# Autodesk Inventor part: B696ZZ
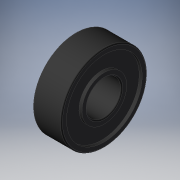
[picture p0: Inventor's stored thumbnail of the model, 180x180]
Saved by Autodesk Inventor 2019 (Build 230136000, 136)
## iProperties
Created: 2022-11
Part Number: B696ZZ
Material: Generic
Catalog Web Link: www.cadenas.de
Description: B6 _ _ ZZ, B6 _ _ AZZ, SB6 _ _ ZZ, SB6 _ _ AZZ, BR _ _ ZZ, SBR _ _ ZZ-Small Ball Bearings - Double Shield Type
Vendor: MISUMI
Document SubType Name: Modeling
Designer: psAdmin
Manufacturer: MISUMI
Mass: 0.647818 g
Surface Area: 6.84496 cm^2
Volume: 0.647818 cm^3
Density: 1 g/cm^3
Appearance: PSOLRGB-175-175-175
Category: PARTsolutions
Company: MISUMI
Title: B696ZZ
Author: Cadenas PARTsolutions
Comments: Small Ball Bearings - Double Shield Type
PSOL_IDENT_0: {$CADENAS_DATA/23d-libs/misumi/metric/12_bearing_holders/sb685zz.prj},219 {VTYP=3D},{NB=B696ZZ},{LIN
PSOL_IDENT_1: A=B696ZZ},{NN=B6 _ _ ZZ, B6 _ _ AZZ, SB6 _ _ ZZ, SB6 _ _ AZZ, BR _ _ ZZ, SBR _ _ ZZ},{DATE=30.06.202
PSOL_IDENT_2: 1 12:59:24},{GEOMDATE=23.07.2013 00:00:00},{VERSION=},{LINEID=120},{WBVAR=MAT},{WBNUMERIC=}  {NB=B69
PSOL_IDENT_3: 6ZZ},{LINA=B696ZZ},{KT=DUMMY},{PN=B696ZZ},{MAT=},{BN=696ZZ},{DD=6.0},{A=3.9530},{BB=0.900},{C=0.900}
PSOL_IDENT_4: ,{D=15},{B=5.0},{RR=0.20},{CR=1350},{COR=530},{CRS=1350},{CRSS=1139},{CORS=530},{CORSS=418},{DS=7.60
PSOL_IDENT_5: },{DDHH=13.40},{R=0.20},{MASS=3.8},{X=0},{BN2=B696ZZ}
NB: B696ZZ
NN: B6 _ _ ZZ, B6 _ _ AZZ, SB6 _ _ ZZ, SB6 _ _ AZZ, BR _ _ ZZ, SBR _ _ ZZ
NT: Small Ball Bearings - Double Shield Type
NBSYN: $PN.
LINA: B696ZZ
CATALOG: Misumi
PN: B696ZZ
MAT: 52100 Bearing Steel
BN: 696ZZ
DD: 6
D: 15
B: 5
RR: 0.2
CR: 1350
COR: 530
DS: 7.6
DDHH: 13.4
R: 0.2
MASS: 3.8
X: 0
SUPPLIER: MISUMI
ARTICLENO: B696ZZ
BOMINFO: B696ZZ
CREATOR: CADENAS GmbH
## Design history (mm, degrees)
sketch "Sketch_1"
  geometry: L1 (4.8, 0)-(0.2, 0); L2 (0.2, 3)-(4.8, 3); L3 (5, 3.2)-(5, 3.9); L4 (5, 3.9)-(4.476, 3.9); L5 (4.476, 3.9)-(4.476, 6.6); L6 (4.476, 6.6)-(5, 6.6); L7 (5, 6.6)-(5, 7.3); L8 (4.8, 7.5)-(0.2, 7.5); L9 (0, 7.3)-(0, 6.6); L10 (0, 6.6)-(0.523, 6.6); L11 (0.523, 6.6)-(0.523, 3.9); L12 (0.523, 3.9)-(0, 3.9); L13 (0, 3.9)-(0, 3.2); A1 r 0.2 centre (0.2, 3.2) between (0, 3.2) and (0.2, 3); A2 r 0.2 centre (4.8, 3.2) between (4.8, 3) and (5, 3.2); A3 r 0.2 centre (4.8, 7.3) between (5, 7.3) and (4.8, 7.5); A4 r 0.2 centre (0.2, 7.3) between (0.2, 7.5) and (0, 7.3)
  constraints: 26 end point, 8 point on circle, 4 centre point
revolve "Revolution1" sketch "Sketch_1" stored, may be unused: angle "d0" = 360 deg
node "to_housing_XY"
node "to_housing_YZ"
node "to_housing_ZX"
node "to_housing_X"
node "to_housing_Y"
node "to_housing_Z"
node "to_housing_Center"
node "to_housing_center_XY"
node "to_housing_center_YZ"
node "to_housing_center_ZX"
node "to_housing_center_X"
node "to_housing_center_Y"
node "to_housing_center_Z"
node "to_housing_center_Center"
body "Solid1"
other parameters: "d1" = 0
